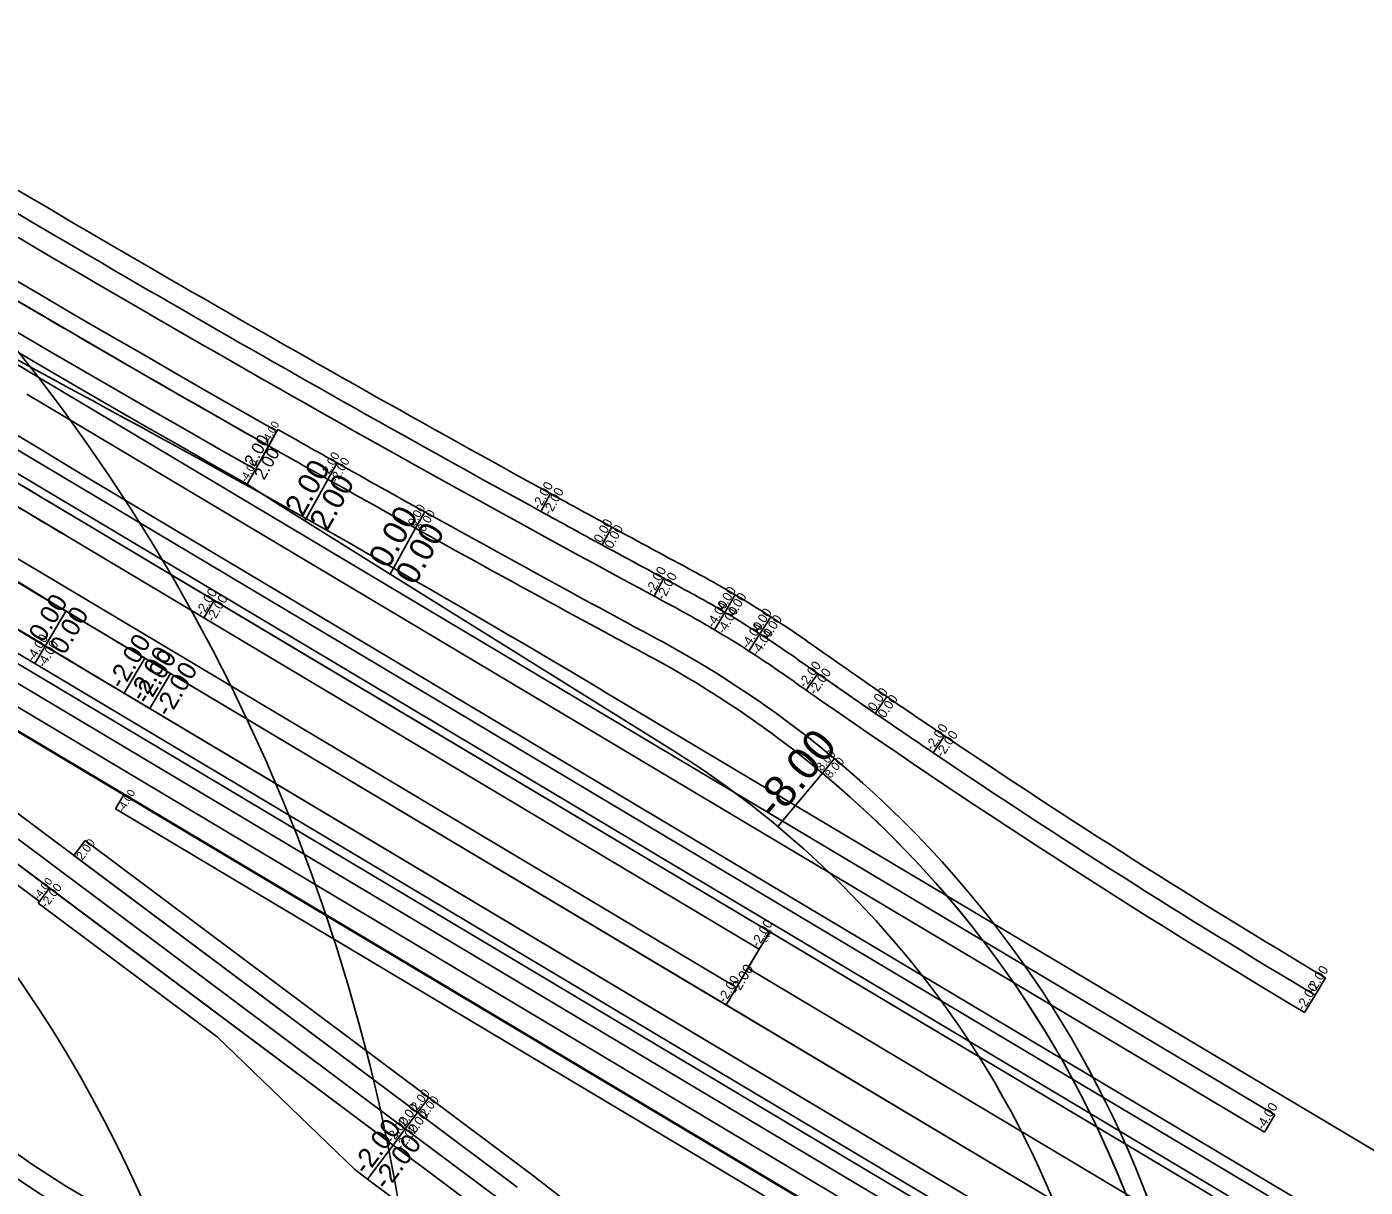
# Model space of a CAD drawing. Extents: x 2342222 to 2351711, y 366548 to 372860.
# Drawn here: x 2346266 to 2347057, y 369511 to 370197 of the extents above; entities that cross this region are included whole.
import ezdxf

# ---------------------------------------------------------------- set-up
doc = ezdxf.new("R2010")
doc.units = 0
for name, color, linetype in [('RD_HC_Cl', 7, 'Continuous'), ('RD_PD_Final_LnLine', 7, 'Continuous'), ('RD_PD_PaveShd', 7, 'Continuous'), ('RD_PD_SuperShp_BL_EB_526', 7, 'Continuous'), ('RD_PD_SuperShp_BL_WB_526', 7, 'Continuous'), ('RD_PD_SuperShp_EB_526', 7, 'Continuous'), ('RD_PD_SuperShp_LINE-A', 7, 'Continuous'), ('RD_PD_SuperShp_Line-B', 7, 'Continuous'), ('RD_PD_SuperShp_REL_L-2118', 7, 'Continuous'), ('RD_PD_SuperShp_REL_L-2523', 7, 'Continuous'), ('RD_PD_SuperShp_REL_LINE-3', 7, 'Continuous'), ('RD_PD_SuperShp_WB_526', 7, 'Continuous')]:
    doc.layers.add(name, color=color, linetype=linetype)

msp = doc.modelspace()

# ---------------------------------------------------------------- linework, layer by layer
at = {"layer": 'RD_HC_Cl'}
msp.add_line((2346606.48, 369804.53), (2348463.13, 368696.8), dxfattribs=at)
msp.add_line((2346606.48, 369804.53), (2348463.13, 368696.8), dxfattribs=at)
for centre, radius, start, end in [((2349158.41, 375253.94), 6000, 236.195282, 241.602511), ((2349158.41, 375253.94), 6000, 236.195282, 241.602511), ((2345401.07, 369318.89), 1100, 337.175, 58.13524), ((2345401.07, 369318.89), 1100, 337.175, 58.13524), ((2342405.09, 362762.64), 8200, 59.178507, 61.602511), ((2342405.09, 362762.64), 8200, 59.178507, 61.602511), ((2345603.44, 369178.93), 800, 339.77456, 51.32478), ((2345603.44, 369178.93), 800, 339.77456, 51.32478)]:
    msp.add_arc(centre, radius, start, end, dxfattribs=at)
at = {"layer": 'RD_PD_Final_LnLine'}
msp.add_line((2346236.75, 369794.56), (2347945.19, 368775.26), dxfattribs=at)
msp.add_line((2346236.75, 369794.56), (2347945.19, 368775.26), dxfattribs=at)
at = {"layer": 'RD_PD_PaveShd'}
for p, q in [((2346272.33, 369990.12), (2347003.26, 369554.02)), ((2346266.18, 369979.81), (2346997.11, 369543.72)), ((2346288.32, 369896.74), (2346698.81, 369651.82)), ((2346698.81, 369651.82), (2346691.47, 369639.51))]:
    msp.add_line(p, q, dxfattribs=at)
for radius, start, end in [(11445.99, 233.263715, 239.178507), (11374.16, 238.446982, 238.868304)]:
    msp.add_arc((2352152.85, 379726.19), radius, start, end, dxfattribs=at)
at = {"layer": 'RD_PD_SuperShp_BL_EB_526'}
for p, q in [((2346685.32, 369629.21), (2346274.83, 369874.12)), ((2346268.68, 369863.82), (2346289.29, 369851.52)), ((2346268.68, 369863.82), (2346679.17, 369618.91)), ((2346289.29, 369851.52), (2346276.99, 369830.91)), ((2346276.99, 369830.91), (2346289.29, 369851.52)), ((2346289.29, 369851.52), (2346351.12, 369814.63)), ((2346276.99, 369830.91), (2346256.38, 369843.21)), ((2346276.99, 369830.91), (2346256.38, 369843.21)), ((2346250.23, 369832.9), (2346270.85, 369820.6)), ((2346276.99, 369830.91), (2346270.85, 369820.6)), ((2346270.85, 369820.6), (2346276.99, 369830.91)), ((2346338.83, 369794.02), (2346276.99, 369830.91)), ((2348273.55, 368639.71), (2346276.99, 369830.91)), ((2346270.85, 369820.6), (2348267.44, 368629.38)), ((2346351.12, 369814.63), (2346338.83, 369794.02)), ((2346338.83, 369794.02), (2346351.12, 369814.63)), ((2346351.12, 369814.63), (2348285.99, 368660.23)), ((2348273.55, 368639.71), (2346338.83, 369794.02)), ((2346692.07, 369640.52), (2346685.32, 369629.21)), ((2347092.44, 369401.64), (2346692.07, 369640.52)), ((2346679.17, 369618.91), (2346685.32, 369629.21)), ((2346685.32, 369629.21), (2346679.17, 369618.9)), ((2346679.17, 369618.9), (2347079.55, 369380.03))]:
    msp.add_line(p, q, dxfattribs=at)
for radius, start in [(11472.33, 233.263715), (11484.33, 238.939044), (11484.33, 238.939044)]:
    msp.add_arc((2352152.85, 379726.19), radius, start, 239.178507, dxfattribs=at)
at = {"layer": 'RD_PD_SuperShp_BL_WB_526'}
for p, q in [((2347003.26, 369554.02), (2346272.33, 369990.12)), ((2346266.15, 369979.83), (2346997.11, 369543.72)), ((2348323.93, 368724.15), (2346306.76, 369927.65)), ((2346294.47, 369907.04), (2348311.78, 368703.46)), ((2346376.91, 369857.85), (2346294.47, 369907.04)), ((2346288.32, 369896.74), (2346370.76, 369847.55)), ((2346370.76, 369847.55), (2346376.91, 369857.85)), ((2346376.91, 369857.85), (2346370.76, 369847.55)), ((2346704.96, 369662.13), (2346376.91, 369857.85)), ((2346370.76, 369847.55), (2346698.81, 369651.83)), ((2346698.81, 369651.83), (2346704.96, 369662.13)), ((2346704.96, 369662.13), (2346701.6, 369656.5)), ((2347105.34, 369423.25), (2346704.96, 369662.13)), ((2346701.6, 369656.5), (2346698.81, 369651.82)), ((2346698.81, 369651.82), (2346692.07, 369640.52)), ((2346692.07, 369640.52), (2347092.44, 369401.64)), ((2346997.11, 369543.72), (2347003.26, 369554.02))]:
    msp.add_line(p, q, dxfattribs=at)
for radius, start, end in [(11409.99, 233.263715, 239.178507), (11433.99, 233.263715, 239.178507), (11374.16, 238.446995, 238.868304), (11433.99, 238.939025, 239.178507), (11445.99, 238.939025, 239.178507)]:
    msp.add_arc((2352152.85, 379726.19), radius, start, end, dxfattribs=at)
at = {"layer": 'RD_PD_SuperShp_EB_526'}
for p, q in [((2346323.62, 369803.09), (2346335.92, 369823.7)), ((2346335.92, 369823.7), (2346323.62, 369803.09)), ((2346335.92, 369823.7), (2346335.62, 369823.88)), ((2348285.94, 368660.26), (2346335.92, 369823.7)), ((2346323.32, 369803.27), (2346323.62, 369803.09)), ((2346323.32, 369803.27), (2348273.49, 368639.75)), ((2346323.62, 369803.09), (2348273.49, 368639.75))]:
    msp.add_line(p, q, dxfattribs=at)
for radius, start in [(11483.16, 233.263715), (11459.16, 238.698285), (11483.16, 238.6991)]:
    msp.add_arc((2352206.89, 379664.63), radius, start, 239.178507, dxfattribs=at)
at = {"layer": 'RD_PD_SuperShp_LINE-A'}
for p, q in [((2346408.99, 369949.2), (2346413.93, 369957.9)), ((2346413.93, 369957.9), (2346409.09, 369949.15)), ((2346414.48, 369958.88), (2346413.93, 369957.9)), ((2346401.15, 369935.26), (2346408.99, 369949.2)), ((2346409.09, 369949.15), (2346401.15, 369935.26)), ((2346444.04, 369929.41), (2346449.49, 369939.1)), ((2346449.49, 369939.1), (2346444.04, 369929.41)), ((2346396.22, 369926.56), (2346401.15, 369935.26)), ((2346401.15, 369935.26), (2346396.26, 369926.53)), ((2346444.04, 369929.41), (2346430.3, 369904.98)), ((2346430.3, 369904.98), (2346444.04, 369929.41)), ((2346396.26, 369926.53), (2346413.03, 369915.75)), ((2346413.03, 369915.75), (2346430.3, 369904.98)), ((2346495.76, 369900.48), (2346501.17, 369910.21)), ((2346501.17, 369910.21), (2346495.76, 369900.48)), ((2346430.3, 369904.98), (2346480.76, 369873.49)), ((2346480.76, 369873.49), (2346495.76, 369900.48)), ((2346495.76, 369900.48), (2346480.76, 369873.49)), ((2346480.76, 369873.49), (2346645.94, 369770.43)), ((2346736.08, 369755.85), (2346743.2, 369764.39)), ((2346743.2, 369764.39), (2346736.08, 369755.85)), ((2346709.74, 369724.26), (2346736.08, 369755.85)), ((2346736.08, 369755.85), (2346709.74, 369724.26))]:
    msp.add_line(p, q, dxfattribs=at)
for centre, radius, start, end in [((2352034, 379865.62), 11390.7, 232.99132, 240.436294), ((2352034, 379865.62), 11416.7, 232.99132, 240.436588), ((2352034, 379865.62), 11416.7, 232.99132, 240.436588), ((2352034, 379865.62), 11426.7, 232.99132, 240.436588), ((2352034, 379865.62), 11400.7, 239.107238, 240.436286), ((2352034, 379865.62), 11400.7, 239.534235, 240.036799), ((2352034, 379865.62), 11400.7, 240.036799, 240.436286), ((2352034, 379865.62), 11389.58, 240.436286, 240.638568), ((2352034, 379865.62), 11400.7, 240.436839, 240.539362), ((2352034, 379865.62), 11400.7, 240.436839, 240.539362), ((2352034, 379865.62), 11400.7, 240.539362, 240.638568), ((2352034, 379865.62), 11400.7, 240.539362, 240.638568), ((2352034, 379865.62), 11389.58, 240.638568, 240.936387), ((2352034, 379865.62), 11400.7, 240.638568, 240.936387), ((2352034, 379865.62), 11400.7, 240.638568, 240.936387), ((2352034, 379865.62), 11389.58, 240.936387, 241.724919), ((2352034, 379865.62), 11400.7, 240.936387, 241.041926), ((2352034, 379865.62), 11400.7, 240.936387, 241.041926), ((2352034, 379865.62), 11400.7, 241.041926, 241.544489), ((2352034, 379865.62), 11400.7, 241.041926, 241.544489), ((2352034, 379865.62), 11400.7, 241.544489, 241.724919), ((2352034, 379865.62), 11400.7, 241.544489, 241.724919), ((2346341.62, 369282.71), 627.13, 50.18223, 61.72492), ((2346341.62, 369282.71), 616, 55.76299, 61.72492), ((2346341.62, 369282.71), 616, 55.76299, 61.72492), ((2346341.62, 369282.71), 616, 50.18223, 55.76299), ((2346341.62, 369282.71), 616, 50.18223, 55.76299), ((2346341.62, 369282.71), 574.88, 50.18223, 58.03805), ((2346341.62, 369282.71), 627.13, 347.0341, 50.18223), ((2346341.62, 369282.71), 616, 347.0341, 50.18223), ((2346341.62, 369282.71), 616, 25.02373, 50.18223), ((2346341.62, 369282.71), 574.88, 347.0341, 50.18223), ((2346341.62, 369282.71), 616, 347.0341, 25.02373)]:
    msp.add_arc(centre, radius, start, end, dxfattribs=at)
at = {"layer": 'RD_PD_SuperShp_Line-B'}
for p, q in [((2345717.08, 370123.86), (2346489.72, 369545.67)), ((2346489.72, 369545.67), (2345717.08, 370123.86)), ((2346482.53, 369536.06), (2345709.89, 370114.25)), ((2346279.58, 369687.94), (2345710.88, 370113.51)), ((2345704.89, 370105.5), (2346273.58, 369679.94)), ((2346300.63, 369716.06), (2346293.96, 369707.15)), ((2346503.58, 369564.19), (2346300.63, 369716.06)), ((2346293.96, 369707.15), (2346496.91, 369555.28)), ((2346279.58, 369687.94), (2346272.91, 369679.03)), ((2346273.59, 369679.93), (2346279.58, 369687.94)), ((2346482.53, 369536.06), (2346279.58, 369687.94)), ((2346272.91, 369679.03), (2346378.63, 369599.93)), ((2346378.63, 369599.93), (2346459.91, 369521.61)), ((2346496.91, 369555.28), (2346503.58, 369564.19)), ((2346503.58, 369564.19), (2346496.91, 369555.28)), ((2346562.54, 369520.07), (2346503.58, 369564.19)), ((2346489.72, 369545.67), (2346496.91, 369555.28)), ((2346496.91, 369555.28), (2346489.72, 369545.67)), ((2346496.91, 369555.28), (2346555.87, 369511.16)), ((2346496.91, 369555.28), (2346555.87, 369511.16)), ((2346489.72, 369545.67), (2346482.53, 369536.06)), ((2346482.53, 369536.06), (2346489.72, 369545.67)), ((2346548.69, 369501.55), (2346489.72, 369545.67)), ((2346489.72, 369545.67), (2346548.69, 369501.55)), ((2346467.48, 369515.95), (2346482.53, 369536.06)), ((2346482.53, 369536.06), (2346467.48, 369515.95)), ((2346541.5, 369491.94), (2346482.53, 369536.06)), ((2346541.5, 369491.94), (2346482.53, 369536.06)), ((2346459.91, 369521.61), (2346467.48, 369515.95)), ((2346467.48, 369515.95), (2346526.44, 369471.83))]:
    msp.add_line(p, q, dxfattribs=at)
msp.add_lwpolyline([(2345882.78, 370014.85), (2346496.91, 369555.28)], dxfattribs=at)
msp.add_arc((2346182.01, 369011.56), 635.13, 47.63463, 53.19179, dxfattribs=at)
at = {"layer": 'RD_PD_SuperShp_REL_L-2118'}
for radius in [538, 550, 550, 562]:
    msp.add_arc((2346569.92, 369970.88), radius, 219.20131, 257.76033, dxfattribs=at)
at = {"layer": 'RD_PD_SuperShp_REL_L-2523'}
for p, q in [((2346569.67, 369910.5), (2346575.45, 369921.02)), ((2346575.45, 369921.02), (2346569.67, 369910.5)), ((2346605.97, 369890.66), (2346611.71, 369901.2)), ((2346611.71, 369901.2), (2346605.97, 369890.66)), ((2346636.66, 369860.38), (2346642.36, 369870.94)), ((2346642.36, 369870.94), (2346636.66, 369860.38)), ((2346678.52, 369850.83), (2346684.64, 369861.15)), ((2346684.64, 369861.15), (2346678.52, 369850.83)), ((2346672.4, 369840.51), (2346678.52, 369850.83)), ((2346678.52, 369850.83), (2346672.4, 369840.51)), ((2346699.14, 369838.08), (2346705.64, 369848.17)), ((2346705.64, 369848.17), (2346699.14, 369838.08)), ((2346692.65, 369827.99), (2346699.14, 369838.08)), ((2346699.14, 369838.08), (2346692.65, 369827.99)), ((2346726.43, 369804.91), (2346733.31, 369814.74)), ((2346733.31, 369814.74), (2346726.43, 369804.91)), ((2346767.31, 369791.16), (2346774.1, 369801.04)), ((2346774.1, 369801.04), (2346767.31, 369791.16)), ((2346801.5, 369767.87), (2346808.21, 369777.82)), ((2346808.21, 369777.82), (2346801.5, 369767.87)), ((2347027.03, 369624.66), (2347033.18, 369634.96)), ((2347020.88, 369614.35), (2347027.03, 369624.66))]:
    msp.add_line(p, q, dxfattribs=at)
for centre, radius, start, end in [((2352034, 379865.62), 11368.2, 238.367606, 241.655293), ((2352034, 379865.62), 11344.2, 238.706299, 241.237792), ((2352034, 379865.62), 11356.2, 238.706299, 241.237792), ((2352034, 379865.62), 11356.2, 238.706299, 241.237792), ((2352034, 379865.62), 11344.2, 241.237792, 241.446517), ((2352034, 379865.62), 11356.2, 241.237792, 241.446517), ((2352034, 379865.62), 11356.2, 241.237792, 241.446517), ((2352034, 379865.62), 11344.2, 241.446517, 241.724919), ((2352034, 379865.62), 11356.2, 241.446517, 241.724919), ((2352034, 379865.62), 11356.2, 241.446517, 241.655293), ((2346341.62, 369282.71), 672.5, 59.33248, 61.72492), ((2352034, 379865.62), 11356.2, 241.655293, 241.724919), ((2352034, 379865.62), 11368.2, 241.655293, 241.724919), ((2346341.62, 369282.71), 660.5, 59.33248, 61.72492), ((2346341.62, 369282.71), 660.5, 59.33248, 61.72492), ((2346341.62, 369282.71), 672.5, 57.22889, 59.33248), ((2346341.62, 369282.71), 648.5, 59.33248, 61.72492), ((2346341.62, 369282.71), 660.5, 57.22889, 59.33248), ((2346341.62, 369282.71), 660.5, 57.22889, 59.33248), ((2346341.62, 369282.71), 672.5, 54.83658, 57.22889), ((2346341.62, 369282.71), 648.5, 57.22889, 59.33248), ((2346341.62, 369282.71), 660.5, 54.83658, 57.22889), ((2346341.62, 369282.71), 660.5, 54.83658, 57.22889), ((2346341.62, 369282.71), 648.5, 54.83658, 57.22889), ((2349486.38, 373746.74), 4788, 234.83658, 235.49526), ((2349486.38, 373746.74), 4800, 234.83658, 235.49526), ((2349486.38, 373746.74), 4800, 234.83658, 235.00133), ((2349486.38, 373746.74), 4812, 234.83658, 235.00133), ((2349486.38, 373746.74), 4800, 235.00133, 235.49526), ((2349486.38, 373746.74), 4812, 235.00133, 239.17843), ((2349486.38, 373746.74), 4788, 235.49526, 235.98908), ((2349486.38, 373746.74), 4800, 235.49526, 235.98908), ((2349486.38, 373746.74), 4800, 235.49526, 235.98908), ((2349486.38, 373746.74), 4788, 235.98908, 239.17851), ((2349486.38, 373746.74), 4800, 235.98908, 239.17843), ((2349486.38, 373746.74), 4800, 235.98908, 239.17843)]:
    msp.add_arc(centre, radius, start, end, dxfattribs=at)
at = {"layer": 'RD_PD_SuperShp_REL_LINE-3'}
for p, q in [((2347921.67, 368829.56), (2346247.54, 369828.39)), ((2346242.42, 369819.8), (2347800.61, 368890.14)), ((2346242.42, 369819.8), (2347916.54, 368820.98)), ((2347794.46, 368879.84), (2346236.27, 369809.5)), ((2346236.27, 369809.5), (2347871.75, 368833.73)), ((2347865.6, 368823.42), (2346230.12, 369799.19)), ((2346318.55, 369734.79), (2346323.68, 369743.38)), ((2346323.68, 369743.38), (2347904.25, 368800.37)), ((2347899.12, 368791.78), (2346318.55, 369734.79))]:
    msp.add_line(p, q, dxfattribs=at)
at = {"layer": 'RD_PD_SuperShp_WB_526'}
msp.add_line((2346189.94, 369975.03), (2349293.25, 368123.51), dxfattribs=at)
msp.add_lwpolyline([(2349305.54, 368144.11), (2347116.84, 369449.97), (2347110.69, 369439.66), (2346196.09, 369985.34)], dxfattribs=at)

# ---------------------------------------------------------------- texts
at = {"layer": 'RD_PD_SuperShp_BL_EB_526'}
for s, height, rotation, p in [('0.00', 11.04, 59.17851, (2346276.04, 369832.59)), ('0.00', 11.04, 59.17851, (2346288.41, 369825.22)), ('-4.00', 5.52, 59.17851, (2346270.37, 369821.45)), ('-4.00', 5.52, 59.17851, (2346276.55, 369817.76)), ('-2.00', 11.04, 59.17851, (2346337.87, 369795.7)), ('-2.00', 11.04, 59.17851, (2346350.24, 369788.33)), ('-2.00', 6.057, 59.17979, (2346686.17, 369624.72)), ('-2.00', 5.52, 59.17441, (2346678.7, 369619.75))]:
    msp.add_text(s, height=height, rotation=rotation, dxfattribs=at).set_placement(p)
at = {"layer": 'RD_PD_SuperShp_BL_WB_526'}
for s, height, rotation, p in [('-2.00', 5.52, 59.17851, (2346370.28, 369848.39)), ('-2.00', 5.52, 59.17851, (2346376.47, 369844.7)), ('-2.00', 5.52, 59.17851, (2346698.33, 369652.67)), ('-2.00', 3.015, 59.17851, (2346702.02, 369654.27)), ('-4.00', 5.52, 59.15519, (2346996.63, 369544.56))]:
    msp.add_text(s, height=height, rotation=rotation, dxfattribs=at).set_placement(p)
at = {"layer": 'RD_PD_SuperShp_EB_526'}
for p in [(2346322.67, 369804.78), (2346335.03, 369797.4)]:
    msp.add_text('-2.00', height=11.04, rotation=59.17851, dxfattribs=at).set_placement(p)
at = {"layer": 'RD_PD_SuperShp_LINE-A'}
for s, height, rotation, p in [('-4.00', 4.6, 60.42793, (2346408.58, 369949.9)), ('2.00', 7.36, 60.65145, (2346400.5, 369936.38)), ('-2.00', 0.518, 60.51053, (2346414.01, 369957.52)), ('2.00', 7.36, 60.25754, (2346406.33, 369928.62)), ('-2.00', 5.118, 60.63857, (2346443.58, 369930.17)), ('-4.00', 4.6, 60.43659, (2346395.81, 369927.25)), ('2.00', 12.891, 60.63857, (2346429.14, 369906.92)), ('-2.00', 5.118, 60.63857, (2346449.4, 369926.9)), ('2.00', 12.891, 60.63857, (2346443.6, 369898.35)), ('0.00', 5.118, 60.93639, (2346495.3, 369901.25)), ('0.00', 14.204, 60.93639, (2346479.71, 369876.03)), ('0.00', 5.118, 60.93639, (2346501.13, 369898.01)), ('0.00', 14.204, 60.93639, (2346495.43, 369866.22)), ('-8.00', 18.917, 50.18223, (2346708.58, 369727.36)), ('8.00', 5.118, 50.18223, (2346735.77, 369756.69)), ('8.00', 5.118, 50.18223, (2346740.89, 369752.41))]:
    msp.add_text(s, height=height, rotation=rotation, dxfattribs=at).set_placement(p)
at = {"layer": 'RD_PD_SuperShp_Line-B'}
for s, height, p in [('2.00', 5.117, (2346298.95, 369703.98)), ('-4.00', 4.6, (2346273.27, 369680.67)), ('-2.00', 5.118, (2346277.9, 369675.86)), ('2.00', 5.117, (2346496.56, 369556.1)), ('2.00', 5.52, (2346489.34, 369546.56)), ('2.00', 5.117, (2346501.9, 369552.1)), ('-2.00', 11.558, (2346466.68, 369517.81)), ('-2.00', 5.52, (2346482.15, 369536.95)), ('2.00', 5.52, (2346495.1, 369542.25)), ('-2.00', 11.558, (2346478.74, 369508.77)), ('-2.00', 5.52, (2346487.91, 369532.64))]:
    msp.add_text(s, height=height, rotation=53.19179, dxfattribs=at).set_placement(p)
at = {"layer": 'RD_PD_SuperShp_REL_L-2523'}
for s, rotation, p in [('-2.00', 61.23779, (2346569.17, 369911.32)), ('-2.00', 61.23779, (2346575.48, 369907.86)), ('0.00', 61.44652, (2346605.47, 369891.48)), ('0.00', 61.44652, (2346611.79, 369888.04)), ('-2.00', 61.65529, (2346636.15, 369861.2)), ('-2.00', 61.65529, (2346642.49, 369857.79)), ('4.00', 59.33248, (2346678.04, 369851.67)), ('4.00', 59.33248, (2346684.23, 369848)), ('-4.00', 59.33248, (2346671.92, 369841.35)), ('-4.00', 59.33248, (2346678.11, 369837.68)), ('4.00', 57.22889, (2346698.7, 369838.94)), ('-4.00', 57.22889, (2346692.2, 369828.85)), ('4.00', 57.22889, (2346704.75, 369835.04)), ('-4.00', 57.22889, (2346698.25, 369824.95)), ('-2.00', 55.00133, (2346726.01, 369805.79)), ('-2.00', 55.00133, (2346731.91, 369801.66)), ('0.00', 55.49526, (2346766.89, 369792.03)), ('0.00', 55.49526, (2346772.82, 369787.95)), ('-2.00', 55.98908, (2346801.07, 369768.74)), ('-2.00', 55.98908, (2346807.04, 369764.71)), ('-2.00', 59.14678, (2347026.55, 369625.5)), ('-2.00', 59.17843, (2347020.4, 369615.19))]:
    msp.add_text(s, height=5.52, rotation=rotation, dxfattribs=at).set_placement(p)
at = {"layer": 'RD_PD_SuperShp_REL_LINE-3'}
msp.add_text('-4.00', height=4.6, rotation=59.17851, dxfattribs=at).set_placement((2346323.31, 369732.42))

doc.saveas('drawing.dxf')
